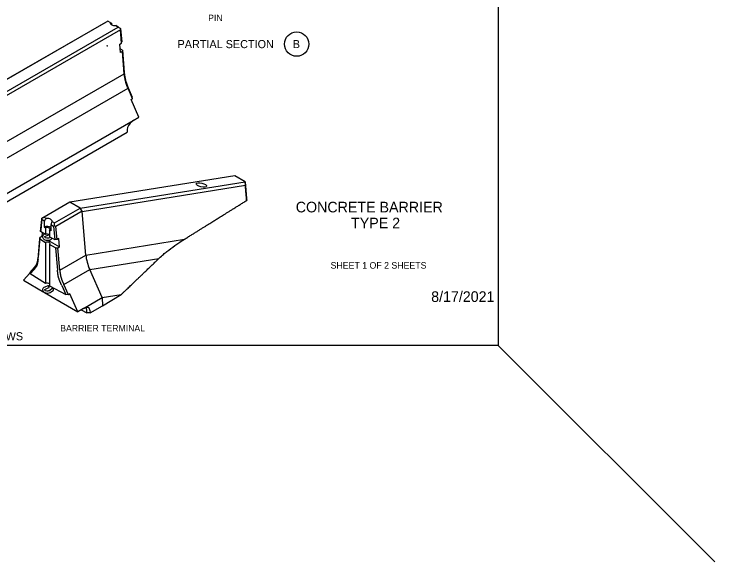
# Model space of a CAD drawing. Extents: x 99862 to 103680, y 99470 to 105076.
# Drawn here: x 101968 to 103680, y 99470 to 100809 of the extents above; entities that cross this region are included whole.
import ezdxf

# ---------------------------------------------------------------- set-up
doc = ezdxf.new("R2010")
doc.units = 0
for name, color, linetype in [('Level 1', 7, 'Continuous'), ('Level 15', 7, 'Continuous'), ('Level 20', 7, 'Continuous'), ('Level 27', 7, 'Continuous'), ('Level 62', 7, 'Continuous'), ('Level 9', 7, 'Continuous')]:
    doc.layers.add(name, color=color, linetype=linetype)

msp = doc.modelspace()

# ---------------------------------------------------------------- linework, layer by layer
at = {"layer": 'Level 1'}
for p, q in [((101361.4, 100310.1), (102193.4, 100790.5)), ((102196.8, 100791.9), (101367.3, 100313)), ((102202.9, 100788.6), (102196.8, 100791.9)), ((102205.4, 100787.1), (102205.4, 100783.4)), ((102222, 100777.3), (102216.2, 100780.8)), ((101392.5, 100298.4), (102222, 100777.3)), ((102227.9, 100770.5), (101395.9, 100290.2)), ((102227.8, 100773.9), (102222, 100777.3)), ((102222.1, 100777.4), (102228, 100773.8)), ((102228, 100773.8), (102227.8, 100773.9)), ((102227.8, 100773.9), (102227.9, 100770.5)), ((102230.6, 100738.1), (102227.9, 100770.5)), ((102228, 100773.8), (102230.7, 100741.4)), ((102196.4, 100731.8), (102193.4, 100730.3)), ((102196.4, 100731.8), (102196.8, 100731.7)), ((102226.3, 100735.7), (102230.6, 100738.1)), ((102228.1, 100715.2), (102226.3, 100735.7)), ((102230.6, 100738.1), (102230.7, 100741.4)), ((102232.4, 100721), (102227.3, 100724.1)), ((102232.3, 100717.7), (102228.1, 100715.2)), ((102232.4, 100721), (102232.3, 100717.7)), ((102236.9, 100663.3), (102232.3, 100717.7)), ((102232.4, 100721), (102237, 100666.2)), ((102257, 100602.3), (102246.1, 100627.8)), ((102246.7, 100628.9), (102256.5, 100606)), ((102253.5, 100600.3), (102257, 100602.3)), ((102272.8, 100556.9), (102253.5, 100600.3)), ((102257, 100602.3), (102256.5, 100606)), ((102258.8, 100548.8), (102272.8, 100556.9)), ((101463.5, 100089.6), (102258.8, 100548.8)), ((102244.1, 100526.8), (102244.1, 100520.1)), ((101479.6, 100078.7), (102244.1, 100520.1)), ((102507.1, 100413.8), (102103.9, 100349.1)), ((102507.1, 100413.8), (102507.2, 100413.8)), ((102532.3, 100399.2), (102507.2, 100413.8)), ((102129.1, 100334.6), (102532.3, 100399.2)), ((102133.8, 100326.8), (102532.8, 100390.7)), ((102532.3, 100399.3), (102535.9, 100358.4)), ((102532.8, 100390.7), (102532.3, 100399.2)), ((102535.9, 100358.4), (102536.1, 100353.5)), ((102035.4, 100310.1), (102099.3, 100347)), ((102103.9, 100349.1), (102041.3, 100313)), ((102066.5, 100298.4), (102129.1, 100334.6)), ((102103.9, 100349.1), (102099.3, 100347)), ((102129.1, 100334.6), (102103.9, 100349.1)), ((102133.8, 100327.1), (102129.1, 100334.6)), ((102133.8, 100327.1), (102069.9, 100290.2)), ((102143.1, 100220), (102133.8, 100326.8)), ((102032.6, 100277.7), (102035.3, 100306.8)), ((102035.4, 100310.1), (102032.7, 100281)), ((102035.3, 100306.8), (102035.5, 100310)), ((102041.2, 100303.2), (102035.3, 100306.8)), ((102035.4, 100310.1), (102035.5, 100310)), ((102035.5, 100310), (102041.3, 100313)), ((102041.2, 100303.2), (102041.2, 100288.6)), ((102041.3, 100313), (102047.1, 100309.4)), ((102060.4, 100301.7), (102066.5, 100298.4)), ((102060.5, 100301.7), (102060.5, 100302.6)), ((102066.9, 100291.8), (102066.5, 100298.4)), ((102041.2, 100288.6), (102044.7, 100286.5)), ((102044.7, 100286.5), (102044.7, 100270.4)), ((102057.9, 100293.5), (102057.9, 100279)), ((102064.2, 100290.1), (102057.9, 100293.5)), ((102066.9, 100291.8), (102064.2, 100290.1)), ((102064.2, 100290.1), (102067.1, 100257.8)), ((102069.9, 100290.2), (102066.9, 100291.8)), ((102072.8, 100257.9), (102069.9, 100290.2)), ((102035.2, 100265.1), (102031, 100262.7)), ((102032.7, 100281), (102032.6, 100277.7)), ((102044.7, 100270.4), (102032.6, 100277.7)), ((102036.2, 100275.5), (102035.2, 100265.1)), ((102035.2, 100265.1), (102037.5, 100263.8)), ((102043.4, 100271.1), (102042.8, 100270.9)), ((102044.7, 100266.3), (102052.7, 100269.7)), ((102054.3, 100280.9), (102054.3, 100264.8)), ((102057.9, 100279), (102054.3, 100280.9)), ((102054.3, 100264.8), (102067.1, 100257.8)), ((102026.3, 100210.3), (102030.9, 100259.4)), ((102031, 100262.7), (102026.4, 100213.9)), ((102030.9, 100259.4), (102031, 100262.7)), ((102030.9, 100259.4), (102044.7, 100251)), ((102044.7, 100251), (102044.7, 100150.7)), ((102050.2, 100256.5), (102078.9, 100239.9)), ((102056.3, 100263.7), (102055.4, 100263)), ((102058.4, 100259.1), (102061, 100261.1)), ((102072.8, 100257.9), (102067.1, 100257.8)), ((102077.1, 100260.4), (102072.8, 100257.9)), ((102078.9, 100239.9), (102077.1, 100260.4)), ((102054.3, 100245.4), (102054.3, 100145.1)), ((102068.9, 100237.4), (102054.3, 100245.4)), ((102068.9, 100237.4), (102074.6, 100237.5)), ((102068.9, 100237.4), (102073.8, 100182.9)), ((102074.6, 100237.5), (102078.9, 100239.9)), ((102079.4, 100183.3), (102074.6, 100237.5)), ((102017.2, 100189.7), (102006.3, 100177.6)), ((102006.8, 100173.9), (102016.6, 100184.8)), ((102183, 100115.9), (102152.6, 100184.6)), ((102006.5, 100176), (101990.5, 100158.4)), ((102006.3, 100177.6), (102006.8, 100173.9)), ((102044.7, 100150.7), (102006.8, 100173.9)), ((101990.5, 100158.4), (102040.6, 100129.5)), ((102050.4, 100144.8), (102042.8, 100141.6)), ((102054.3, 100145.1), (102094.5, 100123.3)), ((102084.1, 100145.8), (102094.5, 100123.3)), ((102100.8, 100123), (102089.3, 100148.1)), ((102042.3, 100128.5), (102123.5, 100081.6)), ((102044.7, 100137), (102052.6, 100140.4)), ((102061.2, 100138.2), (102055.4, 100133.6)), ((102058.4, 100129.7), (102063.9, 100134)), ((102100.8, 100123), (102094.5, 100123.3)), ((102104.3, 100125), (102100.8, 100123)), ((102123.5, 100081.6), (102104.3, 100125)), ((102137.5, 100089.6), (102183, 100115.9)), ((102183, 100115.9), (102229.6, 100123.4)), ((102183, 100115.9), (102183.7, 100096.1)), ((102183.7, 100096.1), (102229.6, 100123.4)), ((102153.6, 100078.7), (102183.7, 100096.1)), ((102137.5, 100089.6), (102123.5, 100081.6)), ((102131.9, 100086.4), (102145.2, 100078.7)), ((102145.2, 100078.7), (102145.2, 100085.2)), ((102153.6, 100078.7), (102145.2, 100078.7)), ((102145.7, 100091.9), (102145.7, 100091.9)), ((102153.2, 100085.2), (102153.6, 100078.7)), ((103150, 100000), (103680.3, 99469.7))]:
    msp.add_line(p, q, dxfattribs=at)
msp.add_lwpolyline([(99862, 99999.5), (103151, 99999.5), (103151, 102075.5), (99862, 102075.5)], close=True, dxfattribs=at)
for centre, major_axis, ratio, start_param, end_param in [((102214.7, 100787.6), (-11.9, 0), 0.57735, 6.15019, 7.986977), ((102214.7, 100782), (11.9, -6.7), 0.012824, 3.281771, 3.821159), ((102214.7, 100782), (11.9, -7.1), 0.012824, 4.853006, 5.392394), ((102259.9, 100536), (13.8, 14.5), 0.529455, 1.308282, 2.634081), ((102259.2, 100535.6), (7.4, 14), 0.600862, 0.762769, 1.007767), ((102048.6, 100297), (-8.6, -14.4), 0.568737, 4.081986, 4.621374), ((102048.6, 100302.6), (-11.9, 0), 0.57735, 3.008597, 4.845385), ((102048.6, 100297), (-8.2, -14.7), 0.585836, 1.661372, 2.200761), ((102048.6, 100283.2), (11.9, 0), 0.57735, 0.672384, 2.24318), ((102048.6, 100283.2), (6.93, 0), 0.57735, 5.670692, 8.466475), ((102048.6, 100267.1), (6.93, 0), 0.57735, 0.612493, 2.183289), ((102048.6, 100247.7), (-6.93, 0), 0.57735, 2.5291, 5.324882), ((102198.8, 100194.6), (39.6, -68.6), 0.57735, 4.031868, 4.529278), ((102048.6, 100147.4), (6.93, 0), 0.57735, 0.612493, 2.183289), ((102137.3, 100076.1), (-13.9, -13.8), 0.555539, 2.694756, 4.020554), ((102138, 100076.4), (7.4, 14), 0.600862, 0.517771, 0.762769), ((102138.7, 100076.1), (4.2, 15.8), 0.317837, 5.412828, 6.198226)]:
    msp.add_ellipse(centre, major_axis=major_axis, ratio=ratio, start_param=start_param, end_param=end_param, dxfattribs=at)
msp.add_ellipse((102425.5, 100391.3), major_axis=(12.8, -3.1), ratio=0.351318, dxfattribs=at)
for points, degree in [([(102246.1, 100627.8), (102244.9, 100630.9), (102242.4, 100637), (102239.8, 100646.1), (102237.8, 100654.9), (102237.2, 100660.5), (102236.9, 100663.3)], 3), ([(102237, 100666.2), (102237.7, 100657.4), (102240.2, 100647.8), (102242.7, 100638.3), (102246.7, 100628.9)], 3), ([(102536.1, 100353.5), (102534.4, 100372.1), (102532.8, 100390.7)], 2), ([(102383.8, 100258.6), (102434.6, 100290.2), (102485.3, 100321.8), (102536.1, 100353.5)], 2), ([(102042.8, 100270.9), (102039.8, 100269.8), (102036.1, 100265.5), (102039.1, 100259.1), (102046.9, 100255.5), (102055.2, 100256.6), (102058.4, 100259.1)], 3), ([(102055.4, 100263), (102053.8, 100261.6), (102047.2, 100260.4), (102042.1, 100263.8), (102042.3, 100264.4), (102043.3, 100265.7), (102044.7, 100266.3)], 3), ([(102052.6, 100269.7), (102052.7, 100269.7), (102052.7, 100269.8), (102052.8, 100269.8), (102052.8, 100269.8), (102052.9, 100269.9), (102053, 100269.9), (102053, 100270), (102053.1, 100270.1), (102053.1, 100270.1)], 3), ([(102321.8, 100211.8), (102330.5, 100220.2), (102340.2, 100228.2), (102361.1, 100243.8), (102372.2, 100251.4), (102383.8, 100258.6)], 3), ([(102017.2, 100189.7), (102022.3, 100195.4), (102025.5, 100203.8), (102026.4, 100213.9)], 2), ([(102026.3, 100210.3), (102025.3, 100199.7), (102021.9, 100190.8), (102016.6, 100184.8)], 2), ([(102229.6, 100123.4), (102260.3, 100152.8), (102291, 100182.3), (102321.8, 100211.8)], 2), ([(102084.1, 100145.8), (102078.4, 100158.2), (102074.8, 100171.1), (102073.8, 100182.9)], 2), ([(102079.4, 100183.3), (102080.4, 100172.1), (102083.8, 100159.8), (102089.3, 100148.1)], 2), ([(102052.6, 100140.4), (102052.7, 100140.4), (102052.7, 100140.4), (102052.8, 100140.4), (102052.8, 100140.5), (102052.9, 100140.5), (102053, 100140.6), (102053, 100140.7), (102053.1, 100140.7), (102053.1, 100140.8), (102053.1, 100140.9), (102053.2, 100141), (102053.2, 100141.1), (102053.2, 100141.2), (102053.2, 100141.3), (102053.2, 100141.4), (102053.3, 100141.5), (102053.3, 100141.6), (102053.2, 100141.7), (102053.2, 100141.8), (102053.2, 100141.9), (102053.2, 100142.1), (102053.2, 100142.2), (102053.1, 100142.3), (102053.1, 100142.4), (102053.1, 100142.6), (102053, 100142.7), (102053, 100142.8), (102052.9, 100142.9), (102052.9, 100143), (102052.8, 100143.2), (102052.7, 100143.3), (102052.7, 100143.4), (102052.6, 100143.5), (102052.5, 100143.6), (102052.4, 100143.7), (102052.3, 100143.8), (102052.3, 100143.9), (102052.2, 100144), (102052.1, 100144.1), (102052, 100144.2), (102051.9, 100144.3), (102051.8, 100144.4), (102051.7, 100144.4), (102051.6, 100144.5), (102051.5, 100144.6), (102051.4, 100144.6), (102051.3, 100144.7), (102051.2, 100144.7), (102051.1, 100144.8), (102051, 100144.8), (102051, 100144.8), (102050.9, 100144.8), (102050.8, 100144.8), (102050.7, 100144.8), (102050.6, 100144.8), (102050.5, 100144.8), (102050.4, 100144.8), (102050.4, 100144.8), (102050.4, 100144.8), (102050.3, 100144.8)], 3), ([(102042.8, 100141.6), (102039.8, 100140.5), (102036.1, 100136.2), (102039.1, 100129.8), (102046.9, 100126.2), (102055.2, 100127.3), (102058.4, 100129.7)], 3), ([(102055.4, 100133.6), (102053.8, 100132.3), (102047.2, 100131.1), (102042.1, 100134.4), (102042.3, 100135.1), (102043.3, 100136.4), (102044.7, 100137)], 3), ([(102064.4, 100135.1), (102064.4, 100135.4), (102064.3, 100135.6), (102064.3, 100135.8), (102064.2, 100136.1), (102064.1, 100136.4), (102064, 100136.6), (102063.9, 100136.8), (102063.7, 100137.1), (102063.6, 100137.3), (102063.4, 100137.5), (102063.2, 100137.7), (102063, 100137.9), (102062.8, 100138), (102062.6, 100138.2), (102062.4, 100138.3), (102062.2, 100138.4), (102062, 100138.4), (102061.8, 100138.4), (102061.7, 100138.4), (102061.5, 100138.4), (102061.3, 100138.3), (102061.3, 100138.3), (102061.3, 100138.3), (102061.2, 100138.2)], 3), ([(102064, 100134.1), (102064, 100134.1), (102064.1, 100134.2), (102064.1, 100134.2), (102064.2, 100134.4), (102064.3, 100134.5), (102064.3, 100134.7), (102064.4, 100134.9), (102064.4, 100135), (102064.4, 100135.1)], 3)]:
    msp.add_open_spline(points, degree=degree, dxfattribs=at)
at = {"layer": 'Level 27'}
for p, q in [((101405.4, 100183.3), (102236.9, 100663.3)), ((101415.3, 100148.1), (102246.1, 100627.8)), ((102143.1, 100220), (102383.8, 100258.6)), ((102079.4, 100183.3), (102143.1, 100220)), ((102152.6, 100184.6), (102321.8, 100211.8)), ((102089.3, 100148.1), (102152.6, 100184.6))]:
    msp.add_line(p, q, dxfattribs=at)
at = {"layer": 'Level 9'}
msp.add_circle((102658.1, 100735.7), 29.7, dxfattribs=at)

# ---------------------------------------------------------------- texts
at = {"layer": 'Level 15'}
msp.add_text('8/17/2021', height=25.98, dxfattribs=at).set_placement((102986.9, 100105.4))
at = {"layer": 'Level 20'}
for s, height, p in [('PIN', 15.84, (102442, 100791.8)), ('PARTIAL SECTION', 19.8, (102367.1, 100725.8)), ('B', 19.8, (102648.6, 100725.8)), ('BARRIER TERMINAL', 15.84, (102080.5, 100033.3)), ('ISOMETRIC VIEWS', 19.8, (101749.9, 100011.6))]:
    msp.add_text(s, height=height, dxfattribs=at).set_placement(p)
at = {"layer": 'Level 62'}
for s, height, p in [('CONCRETE BARRIER', 26, (102656, 100324.3)), ('TYPE 2', 26, (102791.1, 100285.3)), ('SHEET 1 OF 2 SHEETS', 16, (102741.1, 100186.8))]:
    msp.add_text(s, height=height, dxfattribs=at).set_placement(p)

doc.saveas('drawing.dxf')
